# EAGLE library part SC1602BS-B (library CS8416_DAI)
LCD Module SUNLIKE SC1602BS-B
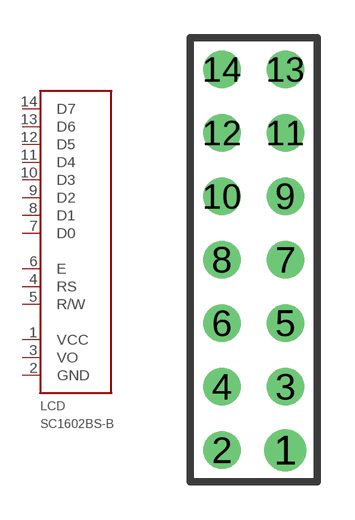
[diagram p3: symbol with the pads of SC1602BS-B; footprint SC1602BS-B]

Designator prefix LCD

## SC1602BS-B  [SC1602BS-B]
1  VCC  pwr
2  GND  pwr
3  VO  in
4  RS  in
5  R/W  in
6  E  in
7  D0  in
8  D1  in
9  D2  in
10  D3  in
11  D4  in
12  D5  in
13  D6  in
14  D7  in

## Footprint SC1602BS-B (pad centres in mm)
LCD Module SC1602BS-B
drill 0.991 pad 1.676 round: 1 1.27,-7.62
drill 0.991 round: 2 -1.27,-7.62; 3 1.27,-5.08; 4 -1.27,-5.08; 5 1.27,-2.54; 6 -1.27,-2.54; 7 1.27,0; 8 -1.27,0; 9 1.27,2.54; 10 -1.27,2.54; 11 1.27,5.08; 12 -1.27,5.08; 13 1.27,7.62; 14 -1.27,7.62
